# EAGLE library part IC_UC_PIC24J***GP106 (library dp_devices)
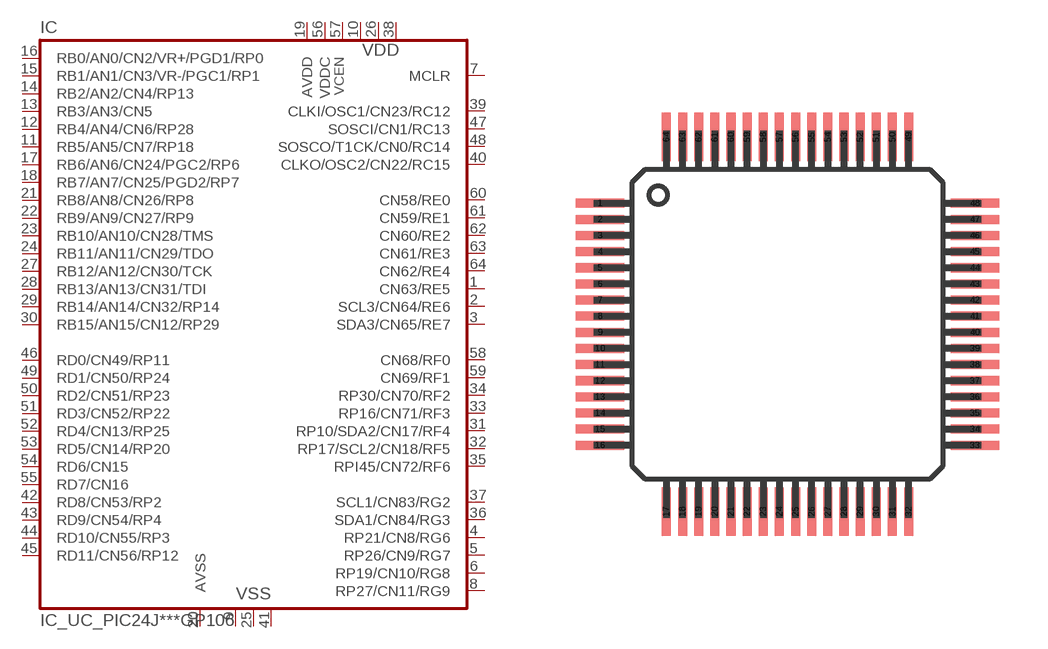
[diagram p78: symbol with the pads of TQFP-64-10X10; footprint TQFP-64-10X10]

Designator prefix IC

## IC_UC_PIC24JGP106  [TQFP-64-10X10]
1  CN63/RE5
2  SCL3/CN64/RE6
3  SDA3/CN65/RE7
4  RP21/CN8/RG6
5  RP26/CN9/RG7
6  RP19/CN10/RG8
7  MCLR  in
8  RP27/CN11/RG9
9  VSS  pwr
10  VDD  pwr
11  RB5/AN5/CN7/RP18
12  RB4/AN4/CN6/RP28
13  RB3/AN3/CN5
14  RB2/AN2/CN4/RP13
15  RB1/AN1/CN3/VR-/PGC1/RP1
16  RB0/AN0/CN2/VR+/PGD1/RP0
17  RB6/AN6/CN24/PGC2/RP6
18  RB7/AN7/CN25/PGD2/RP7
19  AVDD  pwr
20  AVSS  pwr
21  RB8/AN8/CN26/RP8
22  RB9/AN9/CN27/RP9
23  RB10/AN10/CN28/TMS
24  RB11/AN11/CN29/TDO
25  VSS  pwr
26  VDD  pwr
27  RB12/AN12/CN30/TCK
28  RB13/AN13/CN31/TDI
29  RB14/AN14/CN32/RP14
30  RB15/AN15/CN12/RP29
31  RP10/SDA2/CN17/RF4
32  RP17/SCL2/CN18/RF5
33  RP16/CN71/RF3
34  RP30/CN70/RF2
35  RPI45/CN72/RF6
36  SDA1/CN84/RG3
37  SCL1/CN83/RG2
38  VDD  pwr
39  CLKI/OSC1/CN23/RC12
40  CLKO/OSC2/CN22/RC15
41  VSS  pwr
42  RD8/CN53/RP2
43  RD9/CN54/RP4
44  RD10/CN55/RP3
45  RD11/CN56/RP12
46  RD0/CN49/RP11
47  SOSCI/CN1/RC13
48  SOSCO/T1CK/CN0/RC14
49  RD1/CN50/RP24
50  RD2/CN51/RP23
51  RD3/CN52/RP22
52  RD4/CN13/RP25
53  RD5/CN14/RP20
54  RD6/CN15
55  RD7/CN16
56  VDDC  pwr
57  VCEN  pwr
58  CN68/RF0
59  CN69/RF1
60  CN58/RE0
61  CN59/RE1
62  CN60/RE2
63  CN61/RE3
64  CN62/RE4

## Footprint TQFP-64-10X10 (pad centres in mm)
smd 1.5 x 0.28: 1 -5.8,3.75; 2 -5.8,3.25; 3 -5.8,2.75; 4 -5.8,2.25; 5 -5.8,1.75; 6 -5.8,1.25; 7 -5.8,0.75; 8 -5.8,0.25; 9 -5.8,-0.25; 10 -5.8,-0.75; 11 -5.8,-1.25; 12 -5.8,-1.75; 13 -5.8,-2.25; 14 -5.8,-2.75; 15 -5.8,-3.25; 16 -5.8,-3.75; 33 5.8,-3.75; 34 5.8,-3.25; 35 5.8,-2.75; 36 5.8,-2.25; 37 5.8,-1.75; 38 5.8,-1.25; 39 5.8,-0.75; 40 5.8,-0.25; 41 5.8,0.25; 42 5.8,0.75; 43 5.8,1.25; 44 5.8,1.75; 45 5.8,2.25; 46 5.8,2.75; 47 5.8,3.25; 48 5.8,3.75
smd 0.28 x 1.5: 17 -3.75,-5.8; 18 -3.25,-5.8; 19 -2.75,-5.8; 20 -2.25,-5.8; 21 -1.75,-5.8; 22 -1.25,-5.8; 23 -0.75,-5.8; 24 -0.25,-5.8; 25 0.25,-5.8; 26 0.75,-5.8; 27 1.25,-5.8; 28 1.75,-5.8; 29 2.25,-5.8; 30 2.75,-5.8; 31 3.25,-5.8; 32 3.75,-5.8; 49 3.75,5.8; 50 3.25,5.8; 51 2.75,5.8; 52 2.25,5.8; 53 1.75,5.8; 54 1.25,5.8; 55 0.75,5.8; 56 0.25,5.8; 57 -0.25,5.8; 58 -0.75,5.8; 59 -1.25,5.8; 60 -1.75,5.8; 61 -2.25,5.8; 62 -2.75,5.8; 63 -3.25,5.8; 64 -3.75,5.8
